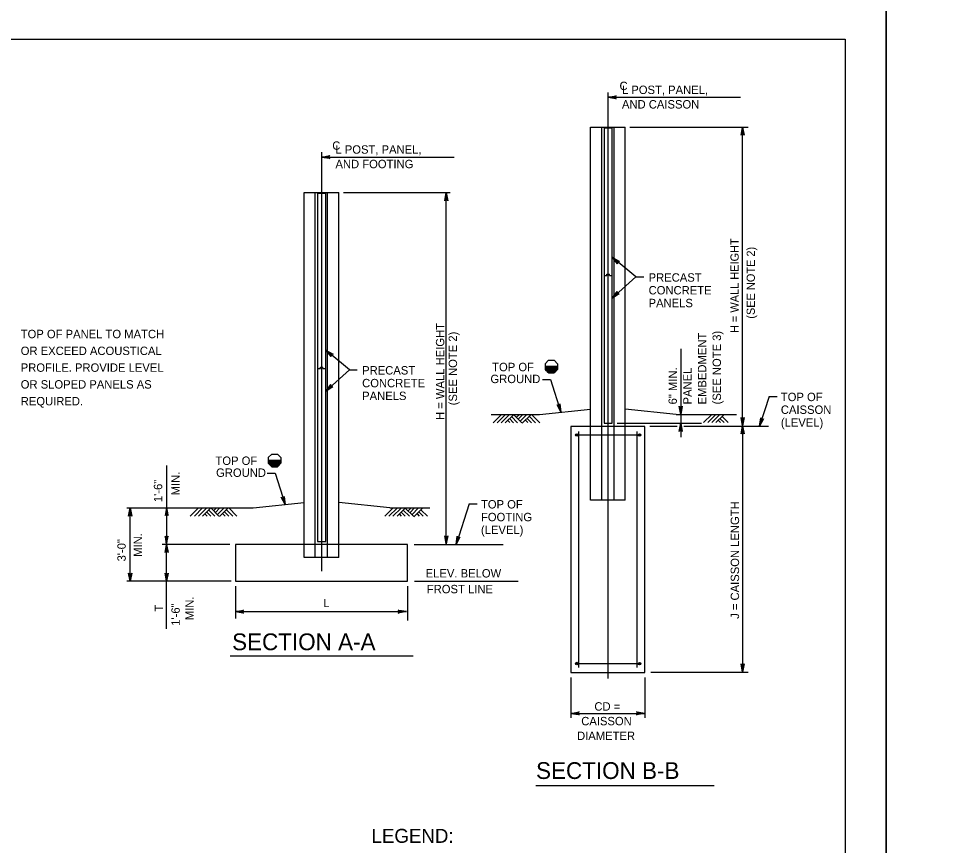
# Model space of a CAD drawing. Extents: x 3761 to 5458, y -616 to 1166.
# Drawn here: x 4284.9 to 4629.5, y 261.8 to 564.2 of the extents above; entities that cross this region are included whole.
import ezdxf

# ---------------------------------------------------------------- set-up
doc = ezdxf.new("R2010")
doc.units = 0
for name, color, linetype in [('1', 7, 'Continuous'), ('2', 7, 'Continuous'), ('PLT-BNDY', 7, 'Continuous')]:
    doc.layers.add(name, color=color, linetype=linetype)

msp = doc.modelspace()

# ---------------------------------------------------------------- linework, layer by layer
at = {"layer": '1'}
for p, q in [((4500.6, 322.83), (4500.6, 537.23)), ((4500.6, 535.47), (4549.01, 535.47)), ((4494.14, 415.14), (4494.14, 524.6)), ((4494.14, 524.6), (4506.89, 524.6)), ((4498.26, 415.14), (4498.26, 524.6)), ((4502.76, 415.14), (4502.76, 524.6)), ((4506.89, 415.14), (4506.89, 524.6)), ((4508.5, 524.6), (4551.85, 524.6)), ((4549.8, 415.26), (4549.8, 524.6)), ((4395.74, 362.03), (4395.74, 515.35)), ((4395.74, 513.59), (4444.29, 513.59)), ((4389.28, 371.89), (4389.28, 500.6)), ((4389.28, 500.6), (4402.03, 500.6)), ((4393.4, 371.89), (4393.4, 500.6)), ((4397.9, 371.89), (4397.9, 500.6)), ((4402.03, 371.89), (4402.03, 500.6)), ((4403.67, 500.6), (4442.76, 500.6)), ((4441.35, 372.02), (4441.35, 500.6)), ((4510.73, 469.72), (4502.1, 476.92)), ((4499.1, 470.22), (4499.1, 416.22)), ((4500.12, 470.22), (4500.12, 470.7)), ((4500.12, 470.7), (4501.08, 470.7)), ((4501.08, 470.22), (4501.08, 470.7)), ((4502.1, 416.22), (4502.1, 470.22)), ((4510.73, 469.72), (4502.1, 461.97)), ((4510.73, 469.72), (4513.63, 469.72)), ((4405.87, 435.75), (4397.24, 442.95)), ((4527.16, 443.49), (4527.16, 411.08)), ((4478.74, 439.24), (4477.49, 437.99)), ((4477.49, 437.99), (4477.49, 435.87)), ((4478.74, 439.24), (4480.86, 439.24)), ((4480.86, 439.24), (4482.11, 437.99)), ((4482.11, 437.99), (4482.11, 435.87)), ((4394.24, 436.25), (4394.24, 372.97)), ((4395.26, 436.25), (4395.26, 436.73)), ((4395.26, 436.73), (4396.22, 436.73)), ((4396.22, 436.25), (4396.22, 436.73)), ((4397.24, 372.97), (4397.24, 436.25)), ((4405.87, 435.75), (4397.24, 428)), ((4405.87, 435.75), (4408.77, 435.75)), ((4477.48, 437.05), (4482.1, 437.05)), ((4477.48, 436.05), (4482.1, 436.05)), ((4477.48, 435.95), (4482.1, 435.95)), ((4477.49, 436.55), (4482.1, 436.55)), ((4477.49, 436.45), (4482.1, 436.45)), ((4477.49, 436.35), (4482.1, 436.35)), ((4477.49, 436.25), (4482.1, 436.25)), ((4477.49, 436.15), (4482.1, 436.15)), ((4478.74, 434.62), (4477.49, 435.87)), ((4477.5, 436.95), (4482.1, 436.95)), ((4477.5, 436.85), (4482.1, 436.85)), ((4477.5, 436.75), (4482.1, 436.75)), ((4477.5, 436.65), (4482.1, 436.65)), ((4477.5, 435.85), (4482.06, 435.85)), ((4477.6, 435.75), (4481.96, 435.75)), ((4477.7, 435.65), (4481.86, 435.65)), ((4477.81, 435.55), (4481.77, 435.55)), ((4477.91, 435.45), (4481.67, 435.45)), ((4478.01, 435.35), (4481.57, 435.35)), ((4478.11, 435.25), (4481.48, 435.25)), ((4478.21, 435.15), (4481.38, 435.15)), ((4478.32, 435.05), (4481.29, 435.05)), ((4478.42, 434.95), (4481.19, 434.95)), ((4478.52, 434.85), (4481.09, 434.85)), ((4478.62, 434.75), (4481, 434.75)), ((4478.72, 434.65), (4480.9, 434.65)), ((4478.74, 434.62), (4480.86, 434.62)), ((4480.59, 437.05), (4482.1, 437.05)), ((4480.86, 434.62), (4482.11, 435.87)), ((4476.58, 432.24), (4479.48, 432.24)), ((4479.48, 432.24), (4483.34, 420.28)), ((4559.55, 425.97), (4556.05, 415.14)), ((4559.55, 425.97), (4562.45, 425.97)), ((4475.47, 419.45), (4494.14, 421.41)), ((4525.55, 419.45), (4506.89, 421.41)), ((4457.84, 419.45), (4475.47, 419.45)), ((4458.46, 416.39), (4461.53, 419.45)), ((4459.96, 416.39), (4463.03, 419.45)), ((4461.46, 416.39), (4464.53, 419.45)), ((4462.96, 416.39), (4466.03, 419.45)), ((4464.64, 416.44), (4463.82, 417.27)), ((4465.97, 416.39), (4464.46, 417.89)), ((4467.47, 416.39), (4465.21, 418.64)), ((4468.97, 416.39), (4465.96, 419.39)), ((4468.12, 419.45), (4466.99, 418.33)), ((4469.38, 419.45), (4467.64, 417.71)), ((4470.88, 419.45), (4468.39, 416.96)), ((4472.38, 419.45), (4469.14, 416.21)), ((4471.23, 416.44), (4470.3, 417.37)), ((4472.56, 416.39), (4470.94, 418)), ((4474.06, 416.39), (4471.69, 418.75)), ((4475.56, 416.39), (4472.49, 419.45)), ((4525.55, 419.45), (4547.58, 419.45)), ((4535.54, 416.43), (4538.54, 419.43)), ((4537.04, 416.43), (4540.04, 419.43)), ((4538.54, 416.43), (4541.54, 419.43)), ((4540.04, 416.43), (4543.04, 419.43)), ((4541.72, 416.49), (4540.9, 417.31)), ((4543.05, 416.43), (4541.54, 417.93)), ((4544.55, 416.43), (4542.29, 418.68)), ((4513.97, 415.02), (4486.97, 415.02)), ((4486.97, 415.02), (4486.97, 325.02)), ((4494.14, 388.03), (4494.14, 415.14)), ((4498.26, 388.03), (4498.26, 415.14)), ((4499.1, 416.22), (4502.1, 416.22)), ((4502.76, 388.03), (4502.76, 415.14)), ((4503.92, 416.22), (4534.79, 416.22)), ((4506.89, 388.03), (4506.89, 415.14)), ((4513.97, 325.02), (4513.97, 415.02)), ((4515.85, 415.14), (4525.85, 415.14)), ((4528.35, 415.14), (4559.27, 415.14)), ((4549.8, 415.26), (4549.8, 325.16)), ((4488.77, 411.91), (4512.11, 411.91)), ((4489.92, 326.8), (4489.92, 413.2)), ((4511.28, 326.8), (4511.28, 413.14)), ((4377.46, 404.93), (4376.21, 403.68)), ((4376.21, 403.68), (4376.21, 401.56)), ((4377.46, 404.93), (4379.57, 404.93)), ((4379.57, 404.93), (4380.83, 403.68)), ((4380.83, 403.68), (4380.83, 401.56)), ((4338.97, 400.71), (4338.97, 371.92)), ((4376.19, 402.74), (4380.81, 402.74)), ((4376.2, 401.94), (4380.81, 401.94)), ((4376.2, 401.84), (4380.81, 401.84)), ((4376.2, 401.74), (4380.81, 401.74)), ((4376.2, 401.64), (4380.81, 401.64)), ((4376.21, 402.44), (4380.81, 402.44)), ((4376.21, 402.34), (4380.81, 402.34)), ((4376.21, 402.24), (4380.81, 402.24)), ((4376.21, 402.14), (4380.81, 402.14)), ((4376.21, 402.04), (4380.81, 402.04)), ((4377.46, 400.31), (4376.21, 401.56)), ((4376.22, 402.64), (4380.81, 402.64)), ((4376.22, 402.54), (4380.81, 402.54)), ((4376.22, 401.54), (4380.77, 401.54)), ((4376.32, 401.44), (4380.67, 401.44)), ((4376.42, 401.34), (4380.58, 401.34)), ((4376.52, 401.24), (4380.48, 401.24)), ((4376.62, 401.14), (4380.39, 401.14)), ((4376.73, 401.04), (4380.29, 401.04)), ((4376.83, 400.94), (4380.19, 400.94)), ((4376.93, 400.84), (4380.1, 400.84)), ((4377.03, 400.74), (4380, 400.74)), ((4377.13, 400.64), (4379.91, 400.64)), ((4377.23, 400.54), (4379.81, 400.54)), ((4377.34, 400.44), (4379.71, 400.44)), ((4377.44, 400.34), (4379.62, 400.34)), ((4377.46, 400.31), (4379.57, 400.31)), ((4379.3, 402.74), (4380.81, 402.74)), ((4379.57, 400.31), (4380.83, 401.56)), ((4375.81, 397.93), (4378.71, 397.93)), ((4378.71, 397.93), (4382.41, 386.44)), ((4370.61, 385.2), (4389.28, 387.16)), ((4420.69, 385.2), (4402.03, 387.16)), ((4449.7, 386.69), (4444.92, 371.89)), ((4449.7, 386.69), (4452.6, 386.69)), ((4506.89, 388.03), (4494.14, 388.03)), ((4324.46, 385.2), (4370.61, 385.2)), ((4325.63, 358.39), (4325.63, 385.2)), ((4347.65, 382.2), (4350.65, 385.2)), ((4349.15, 382.2), (4352.15, 385.2)), ((4350.65, 382.2), (4353.65, 385.2)), ((4352.15, 382.2), (4355.15, 385.2)), ((4353.82, 382.26), (4353, 383.08)), ((4355.15, 382.2), (4353.65, 383.7)), ((4356.65, 382.2), (4354.4, 384.45)), ((4358.15, 382.2), (4355.15, 385.2)), ((4357.23, 385.2), (4356.18, 384.14)), ((4358.5, 385.2), (4356.82, 383.52)), ((4360, 385.2), (4357.57, 382.77)), ((4361.5, 385.2), (4358.32, 382.02)), ((4360.41, 382.26), (4359.59, 383.08)), ((4361.74, 382.2), (4360.24, 383.7)), ((4363.24, 382.2), (4360.99, 384.45)), ((4364.74, 382.2), (4361.74, 385.2)), ((4418.83, 382.16), (4421.83, 385.16)), ((4420.33, 382.16), (4423.33, 385.16)), ((4420.69, 385.2), (4435.28, 385.2)), ((4421.83, 382.16), (4424.83, 385.16)), ((4423.33, 382.16), (4426.33, 385.16)), ((4425.01, 382.22), (4424.18, 383.04)), ((4426.33, 382.16), (4424.83, 383.66)), ((4427.83, 382.16), (4425.58, 384.41)), ((4429.33, 382.16), (4426.33, 385.16)), ((4428.47, 385.2), (4427.36, 384.1)), ((4429.73, 385.2), (4428.01, 383.48)), ((4431.23, 385.2), (4428.76, 382.73)), ((4432.73, 385.2), (4429.51, 381.98)), ((4431.6, 382.22), (4430.77, 383.04)), ((4432.92, 382.16), (4431.42, 383.66)), ((4434.42, 382.16), (4432.17, 384.41)), ((4394.24, 372.97), (4397.24, 372.97)), ((4362.09, 371.89), (4337.4, 371.89)), ((4338.97, 341), (4338.97, 371.86)), ((4427.15, 371.89), (4364.15, 371.89)), ((4364.15, 371.89), (4364.15, 358.39)), ((4389.28, 367.09), (4389.28, 371.89)), ((4393.4, 367.09), (4393.4, 371.89)), ((4397.9, 367.09), (4397.9, 371.89)), ((4402.03, 367.09), (4402.03, 371.89)), ((4427.15, 358.39), (4427.15, 371.89)), ((4429.63, 371.89), (4462.14, 371.89)), ((4402.03, 367.09), (4389.28, 367.09)), ((4362.56, 358.39), (4324.46, 358.39)), ((4364.15, 358.39), (4427.15, 358.39)), ((4429.74, 358.39), (4467.62, 358.39)), ((4364.15, 356.55), (4364.15, 344.7)), ((4427.15, 356.55), (4427.15, 343.97)), ((4364.15, 347.27), (4426.76, 347.27)), ((4362.27, 331.08), (4429.18, 331.08)), ((4488.77, 328.24), (4512.11, 328.24)), ((4486.97, 325.02), (4513.97, 325.02)), ((4516.28, 325.16), (4551.85, 325.16)), ((4486.97, 323.2), (4486.97, 308.38)), ((4513.97, 323.2), (4513.97, 308.38)), ((4486.97, 310.02), (4513.97, 310.02)), ((4474.17, 283.66), (4539.47, 283.66))]:
    msp.add_line(p, q, dxfattribs=at)
for points in [[(4500.6, 535.47), (4503.58, 536.03), (4503.35, 535.87), (4503.23, 535.67), (4503.2, 535.47), (4503.23, 535.27), (4503.35, 535.07), (4503.58, 534.91), (4500.6, 535.47), (4503.35, 535.07), (4503.23, 535.27), (4500.6, 535.47), (4503.2, 535.47), (4503.23, 535.67), (4500.6, 535.47), (4503.35, 535.87)], [(4502.1, 470.22), (4502.1, 524.22), (4499.1, 524.22), (4499.1, 470.22)], [(4549.8, 524.6), (4550.36, 521.62), (4550.2, 521.85), (4550, 521.96), (4549.8, 522), (4549.6, 521.96), (4549.4, 521.85), (4549.24, 521.62), (4549.8, 524.6), (4549.4, 521.85), (4549.6, 521.96), (4549.8, 524.6), (4549.8, 522), (4550, 521.96), (4549.8, 524.6), (4550.2, 521.85)], [(4395.74, 513.59), (4398.72, 514.15), (4398.49, 513.99), (4398.37, 513.79), (4398.34, 513.59), (4398.37, 513.39), (4398.49, 513.19), (4398.72, 513.03), (4395.74, 513.59), (4398.49, 513.19), (4398.37, 513.39), (4395.74, 513.59), (4398.34, 513.59), (4398.37, 513.79), (4395.74, 513.59), (4398.49, 513.99)], [(4397.24, 462.97), (4397.24, 500.22), (4394.24, 500.22), (4394.24, 462.97)], [(4441.35, 500.6), (4441.9, 497.62), (4441.75, 497.85), (4441.55, 497.97), (4441.35, 498), (4441.15, 497.97), (4440.95, 497.85), (4440.79, 497.62), (4441.35, 500.6), (4440.95, 497.85), (4441.15, 497.97), (4441.35, 500.6), (4441.35, 498), (4441.55, 497.97), (4441.35, 500.6), (4441.75, 497.85)], [(4502.1, 476.92), (4504.75, 475.44), (4504.47, 475.47), (4504.25, 475.39), (4504.09, 475.26), (4503.99, 475.08), (4503.96, 474.85), (4504.03, 474.58), (4502.1, 476.92), (4503.96, 474.85), (4503.99, 475.08), (4502.1, 476.92), (4504.09, 475.26), (4504.25, 475.39), (4502.1, 476.92), (4504.47, 475.47)], [(4499.1, 470.22), (4500.12, 470.22)], [(4501.08, 470.22), (4502.1, 470.22)], [(4394.24, 462.97), (4394.24, 436.25)], [(4397.24, 436.25), (4397.24, 462.97)], [(4502.1, 461.97), (4503.94, 464.38), (4503.88, 464.11), (4503.93, 463.88), (4504.03, 463.71), (4504.19, 463.58), (4504.41, 463.51), (4504.69, 463.55), (4502.1, 461.97), (4504.41, 463.51), (4504.19, 463.58), (4502.1, 461.97), (4504.03, 463.71), (4503.93, 463.88), (4502.1, 461.97), (4503.88, 464.11)], [(4397.24, 442.95), (4399.89, 441.47), (4399.61, 441.49), (4399.39, 441.42), (4399.23, 441.28), (4399.13, 441.11), (4399.1, 440.88), (4399.17, 440.61), (4397.24, 442.95), (4399.1, 440.88), (4399.13, 441.11), (4397.24, 442.95), (4399.23, 441.28), (4399.39, 441.42), (4397.24, 442.95), (4399.61, 441.49)], [(4394.24, 436.25), (4395.26, 436.25)], [(4396.22, 436.25), (4397.24, 436.25)], [(4397.24, 428), (4399.08, 430.41), (4399.02, 430.13), (4399.06, 429.91), (4399.17, 429.73), (4399.33, 429.61), (4399.55, 429.54), (4399.83, 429.57), (4397.24, 428), (4399.55, 429.54), (4399.33, 429.61), (4397.24, 428), (4399.17, 429.73), (4399.06, 429.91), (4397.24, 428), (4399.02, 430.13)], [(4483.34, 420.28), (4481.89, 422.94), (4482.12, 422.78), (4482.34, 422.72), (4482.54, 422.75), (4482.72, 422.85), (4482.88, 423.02), (4482.96, 423.29), (4483.34, 420.28), (4482.88, 423.02), (4482.72, 422.85), (4483.34, 420.28), (4482.54, 422.75), (4482.34, 422.72), (4483.34, 420.28), (4482.12, 422.78)], [(4527.16, 419.45), (4526.6, 422.43), (4526.76, 422.2), (4526.96, 422.08), (4527.16, 422.05), (4527.36, 422.08), (4527.56, 422.2), (4527.72, 422.43), (4527.16, 419.45), (4527.56, 422.2), (4527.36, 422.08), (4527.16, 419.45), (4527.16, 422.05), (4526.96, 422.08), (4527.16, 419.45), (4526.76, 422.2)], [(4549.8, 415.26), (4549.24, 418.25), (4549.4, 418.02), (4549.6, 417.9), (4549.8, 417.86), (4550, 417.9), (4550.2, 418.02), (4550.36, 418.25), (4549.8, 415.26), (4550.2, 418.02), (4550, 417.9), (4549.8, 415.26), (4549.8, 417.86), (4549.6, 417.9), (4549.8, 415.26), (4549.4, 418.02)], [(4556.05, 415.14), (4556.44, 418.15), (4556.52, 417.88), (4556.67, 417.71), (4556.85, 417.61), (4557.05, 417.58), (4557.28, 417.63), (4557.5, 417.8), (4556.05, 415.14), (4557.28, 417.63), (4557.05, 417.58), (4556.05, 415.14), (4556.85, 417.61), (4556.67, 417.71), (4556.05, 415.14), (4556.52, 417.88)], [(4527.16, 416.22), (4527.72, 413.24), (4527.56, 413.47), (4527.36, 413.58), (4527.16, 413.62), (4526.96, 413.58), (4526.76, 413.47), (4526.6, 413.24), (4527.16, 416.22), (4526.76, 413.47), (4526.96, 413.58), (4527.16, 416.22), (4527.16, 413.62), (4527.36, 413.58), (4527.16, 416.22), (4527.56, 413.47)], [(4549.8, 415.26), (4550.36, 412.28), (4550.2, 412.51), (4550, 412.63), (4549.8, 412.66), (4549.6, 412.63), (4549.4, 412.51), (4549.24, 412.28), (4549.8, 415.26), (4549.4, 412.51), (4549.6, 412.63), (4549.8, 415.26), (4549.8, 412.66), (4550, 412.63), (4549.8, 415.26), (4550.2, 412.51)], [(4382.41, 386.44), (4380.97, 389.11), (4381.19, 388.94), (4381.41, 388.89), (4381.61, 388.92), (4381.79, 389.01), (4381.95, 389.19), (4382.03, 389.45), (4382.41, 386.44), (4381.95, 389.19), (4381.79, 389.01), (4382.41, 386.44), (4381.61, 388.92), (4381.41, 388.89), (4382.41, 386.44), (4381.19, 388.94)], [(4325.63, 385.2), (4326.19, 382.22), (4326.03, 382.45), (4325.83, 382.57), (4325.63, 382.6), (4325.43, 382.57), (4325.23, 382.45), (4325.07, 382.22), (4325.63, 385.2), (4325.23, 382.45), (4325.43, 382.57), (4325.63, 385.2), (4325.63, 382.6), (4325.83, 382.57), (4325.63, 385.2), (4326.03, 382.45)], [(4338.97, 385.39), (4338.41, 382.41), (4338.57, 382.64), (4338.77, 382.75), (4338.97, 382.79), (4339.17, 382.75), (4339.37, 382.64), (4339.52, 382.41), (4338.97, 385.39), (4339.37, 382.64), (4339.17, 382.75), (4338.97, 385.39), (4338.97, 382.79), (4338.77, 382.75), (4338.97, 385.39), (4338.57, 382.64)], [(4338.97, 371.92), (4339.52, 374.9), (4339.37, 374.67), (4339.17, 374.56), (4338.97, 374.52), (4338.77, 374.56), (4338.57, 374.67), (4338.41, 374.9), (4338.97, 371.92), (4338.57, 374.67), (4338.77, 374.56), (4338.97, 371.92), (4338.97, 374.52), (4339.17, 374.56), (4338.97, 371.92), (4339.37, 374.67)], [(4441.35, 372.02), (4440.79, 375), (4440.95, 374.77), (4441.15, 374.65), (4441.35, 374.62), (4441.55, 374.65), (4441.75, 374.77), (4441.9, 375), (4441.35, 372.02), (4441.75, 374.77), (4441.55, 374.65), (4441.35, 372.02), (4441.35, 374.62), (4441.15, 374.65), (4441.35, 372.02), (4440.95, 374.77)], [(4444.92, 371.89), (4445.31, 374.9), (4445.39, 374.63), (4445.54, 374.46), (4445.72, 374.36), (4445.92, 374.33), (4446.15, 374.39), (4446.37, 374.56), (4444.92, 371.89), (4446.15, 374.39), (4445.92, 374.33), (4444.92, 371.89), (4445.72, 374.36), (4445.54, 374.46), (4444.92, 371.89), (4445.39, 374.63)], [(4338.97, 371.86), (4339.52, 368.87), (4339.37, 369.1), (4339.17, 369.22), (4338.97, 369.26), (4338.77, 369.22), (4338.57, 369.1), (4338.41, 368.87), (4338.97, 371.86), (4338.57, 369.1), (4338.77, 369.22), (4338.97, 371.86), (4338.97, 369.26), (4339.17, 369.22), (4338.97, 371.86), (4339.37, 369.1)], [(4325.63, 358.39), (4325.07, 361.37), (4325.23, 361.14), (4325.43, 361.02), (4325.63, 360.99), (4325.83, 361.02), (4326.03, 361.14), (4326.19, 361.37), (4325.63, 358.39), (4326.03, 361.14), (4325.83, 361.02), (4325.63, 358.39), (4325.63, 360.99), (4325.43, 361.02), (4325.63, 358.39), (4325.23, 361.14)], [(4338.97, 358.39), (4338.41, 361.37), (4338.57, 361.14), (4338.77, 361.02), (4338.97, 360.99), (4339.17, 361.02), (4339.37, 361.14), (4339.52, 361.37), (4338.97, 358.39), (4339.37, 361.14), (4339.17, 361.02), (4338.97, 358.39), (4338.97, 360.99), (4338.77, 361.02), (4338.97, 358.39), (4338.57, 361.14)], [(4364.15, 347.27), (4367.13, 347.83), (4366.9, 347.67), (4366.79, 347.47), (4366.75, 347.27), (4366.79, 347.07), (4366.9, 346.87), (4367.13, 346.71), (4364.15, 347.27), (4366.9, 346.87), (4366.79, 347.07), (4364.15, 347.27), (4366.75, 347.27), (4366.79, 347.47), (4364.15, 347.27), (4366.9, 347.67)], [(4426.76, 347.27), (4423.78, 346.71), (4424.01, 346.87), (4424.12, 347.07), (4424.16, 347.27), (4424.12, 347.47), (4424.01, 347.67), (4423.78, 347.83), (4426.76, 347.27), (4424.01, 347.67), (4424.12, 347.47), (4426.76, 347.27), (4424.16, 347.27), (4424.12, 347.07), (4426.76, 347.27), (4424.01, 346.87)], [(4549.8, 325.16), (4549.24, 328.14), (4549.4, 327.91), (4549.6, 327.79), (4549.8, 327.76), (4550, 327.79), (4550.2, 327.91), (4550.36, 328.14), (4549.8, 325.16), (4550.2, 327.91), (4550, 327.79), (4549.8, 325.16), (4549.8, 327.76), (4549.6, 327.79), (4549.8, 325.16), (4549.4, 327.91)], [(4486.97, 310.02), (4489.96, 310.58), (4489.73, 310.42), (4489.61, 310.22), (4489.57, 310.02), (4489.61, 309.82), (4489.73, 309.62), (4489.96, 309.46), (4486.97, 310.02), (4489.73, 309.62), (4489.61, 309.82), (4486.97, 310.02), (4489.57, 310.02), (4489.61, 310.22), (4486.97, 310.02), (4489.73, 310.42)], [(4513.97, 310.02), (4510.99, 309.46), (4511.22, 309.62), (4511.34, 309.82), (4511.37, 310.02), (4511.34, 310.22), (4511.22, 310.42), (4510.99, 310.58), (4513.97, 310.02), (4511.22, 310.42), (4511.34, 310.22), (4513.97, 310.02), (4511.37, 310.02), (4511.34, 309.82), (4513.97, 310.02), (4511.22, 309.62)]]:
    msp.add_lwpolyline(points, dxfattribs=at)
for centre, radius in [((4489.12, 411.91), 0.468), ((4489.12, 411.91), 0.354), ((4489.12, 411.91), 0.253), ((4489.12, 411.91), 0.143), ((4512.11, 411.91), 0.468), ((4512.11, 411.91), 0.354), ((4512.11, 411.91), 0.253), ((4512.11, 411.91), 0.143), ((4489.12, 328.25), 0.468), ((4489.12, 328.25), 0.354), ((4489.12, 328.25), 0.253), ((4489.12, 328.25), 0.143), ((4512.11, 328.23), 0.468), ((4512.11, 328.23), 0.354), ((4512.11, 328.23), 0.253), ((4512.11, 328.23), 0.143)]:
    msp.add_circle(centre, radius, dxfattribs=at)
at = {"layer": '2'}
for p, q in [((3801.34, 556.69), (4587.34, 556.69)), ((4587.34, 556.69), (4587.34, -7.31))]:
    msp.add_line(p, q, dxfattribs=at)
at = {"layer": 'PLT-BNDY'}
for points in [[(3761.34, 571.69), (4602.34, 571.69), (4602.34, -22.31), (3761.34, -22.31)], [(4602.34, 571.69), (5443.34, 571.69), (5443.34, -22.31), (4602.34, -22.31)]]:
    msp.add_lwpolyline(points, close=True, dxfattribs=at)

# ---------------------------------------------------------------- texts
at = {"layer": '1'}
for s, height, p in [('C', 3.07, (4504.77, 538.11)), ('L POST, PANEL,', 3.0721, (4505.66, 536.68)), ('AND CAISSON', 3.0721, (4505.66, 531.37)), ('C', 3.07, (4399.62, 516.27)), ('L POST, PANEL,', 3.0721, (4400.78, 514.84)), ('AND FOOTING', 3.0721, (4400.78, 509.53)), ('PRECAST', 3.072, (4515.41, 468.01)), ('CONCRETE', 3.072, (4515.41, 463.34)), ('PANELS', 3.072, (4515.41, 458.66)), ('TOP OF PANEL TO MATCH', 3.072, (4285.58, 447.32)), ('OR EXCEED ACOUSTICAL', 3.072, (4285.58, 441.17)), ('PROFILE. PROVIDE LEVEL', 3.072, (4285.58, 435.03)), ('TOP OF', 3.072, (4458.15, 435.25)), ('PRECAST', 3.072, (4410.55, 434.04)), ('OR SLOPED PANELS AS', 3.072, (4285.58, 428.89)), ('CONCRETE', 3.072, (4410.55, 429.36)), ('GROUND', 3.072, (4457.52, 430.89)), ('PANELS', 3.072, (4410.55, 424.69)), ('TOP OF', 3.072, (4563.82, 424.3)), ('REQUIRED.', 3.072, (4285.58, 422.74)), ('CAISSON', 3.072, (4563.82, 419.63)), ('(LEVEL)', 3.072, (4563.82, 414.95)), ('TOP OF', 3.072, (4356.87, 400.95)), ('GROUND', 3.072, (4357.09, 396.58)), ('TOP OF', 3.072, (4454.05, 385.01)), ('FOOTING', 3.072, (4454.05, 380.34)), ('(LEVEL)', 3.072, (4454.05, 375.67)), ('ELEV. BELOW', 3.0721, (4433.82, 359.76)), ('FROST LINE', 3.072, (4434.23, 353.98)), ('L', 3, (4396.34, 348.9)), ('SECTION A-A', 6.144, (4362.95, 333.15)), ('CD =', 3.072, (4495.57, 311.04)), ('CAISSON', 3.072, (4490.75, 305.67)), ('DIAMETER', 3.072, (4489.22, 300.29)), ('SECTION B-B', 6.144, (4474.21, 286.03)), ('LEGEND:', 5.117, (4413.99, 262.66))]:
    msp.add_text(s, height=height, dxfattribs=at).set_placement(p)
for s, height, p in [('H = WALL HEIGHT', 3, (4548.38, 449.21)), ('(SEE NOTE 2)', 3, (4554.3, 454.46)), ('H = WALL HEIGHT', 3.0721, (4440.63, 417.39)), ('(SEE NOTE 2)', 3.0721, (4445.3, 422.77)), ('EMBEDMENT', 3.072, (4536.53, 423.09)), ('(SEE NOTE 3)', 3.0721, (4541.91, 423.09)), ('6" MIN.', 3.072, (4525.78, 423.09)), ('PANEL', 3.072, (4531.16, 423.09)), ('MIN.', 3.072, (4343.79, 389.82)), ('1\'-6"', 3.072, (4337.38, 387.36)), ('J = CAISSON LENGTH', 3.0721, (4548.53, 344.61)), ('MIN.', 3.072, (4329.99, 367.31)), ('3\'-0"', 3.072, (4324.03, 365.64)), ('MIN.', 3.072, (4348.91, 344.14)), ('T', 3.07, (4337.67, 347.25)), ('1\'-6"', 3.072, (4343.79, 342.1))]:
    msp.add_text(s, height=height, rotation=90, dxfattribs=at).set_placement(p)

doc.saveas('drawing.dxf')
